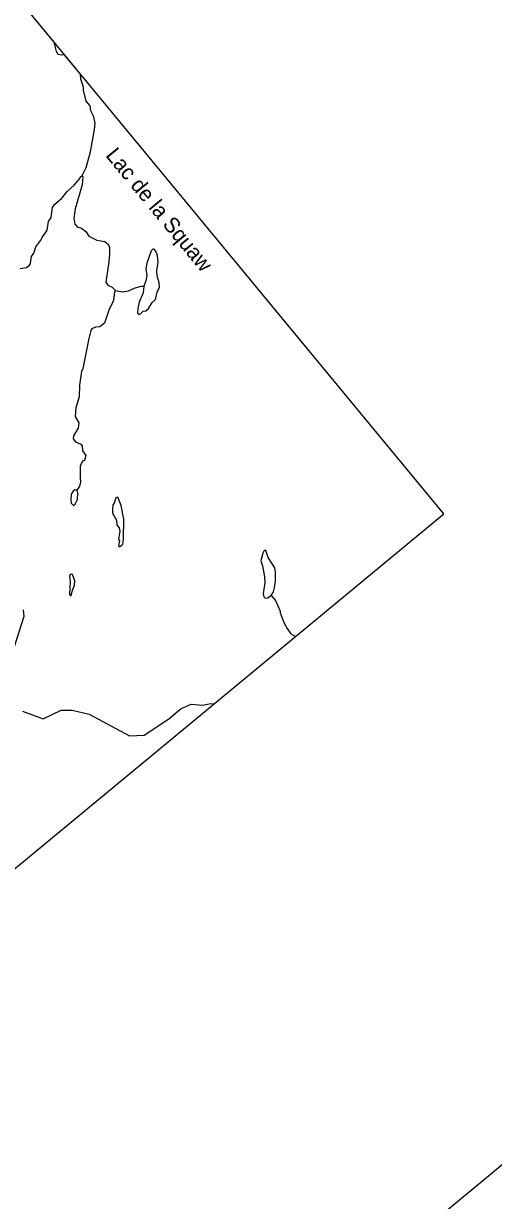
# Model space of a CAD drawing. Extents: x 347312 to 350503, y 6073086 to 6076432.
# Drawn here: x 349803.4 to 349915.2, y 6073732 to 6074011.8 of the extents above; entities that cross this region are included whole.
import ezdxf

# ---------------------------------------------------------------- set-up
doc = ezdxf.new("R2010")
doc.units = 0
doc.layers.add('Level 60', color=7, linetype='Continuous')
doc.layers.add('Level 63', color=7, linetype='Continuous')

msp = doc.modelspace()

# ---------------------------------------------------------------- linework, layer by layer
at = {"layer": 'Level 60'}
msp.add_lwpolyline([(350097.64, 6074648.45), (350470.23, 6074198.33), (349166.42, 6073119.09), (348793.83, 6073569.21)], close=True, dxfattribs=at)
at = {"layer": 'Level 63'}
msp.add_lwpolyline([(349489.82, 6073994.99), (349706.59, 6073732.65), (349903.35, 6073895.24), (349686.57, 6074157.57)], close=True, dxfattribs=at)
for points in [[(349809.31, 6073964.78), (349809.96, 6073965.68), (349810.27, 6073968.09), (349810.82, 6073968.91), (349811.91, 6073969.72), (349812, 6073969.95), (349812.28, 6073970.01), (349813.74, 6073971.93), (349815.43, 6073973.43), (349816.82, 6073974.96), (349816.87, 6073975.32), (349817.37, 6073975.72), (349818.28, 6073977.58), (349819.36, 6073981.36), (349820.31, 6073986.67), (349820.43, 6073988.17), (349820.12, 6073989.66), (349819.4, 6073991.04), (349819.27, 6073992.3), (349818.33, 6073993.35), (349817.67, 6073995.97), (349817.66, 6073996.67), (349817.01, 6073998.59), (349816.96, 6073999.78), (349813.06, 6074004.5), (349813.03, 6074004.45), (349812.53, 6074004.32), (349811.64, 6074004.49), (349811.21, 6074005.18), (349810.68, 6074007.37), (349766.44, 6074060.92)], [(349817.37, 6073975.72), (349817.54, 6073975.36), (349817.37, 6073973.44), (349815.65, 6073967.74), (349815.4, 6073965.59), (349815.62, 6073964.14), (349816.16, 6073963.53), (349817.17, 6073963.14), (349818.18, 6073962.42), (349818.92, 6073961.27), (349820.84, 6073960.29), (349822.77, 6073959.97), (349823.54, 6073959.34), (349823.85, 6073958.6), (349823.83, 6073957.18), (349823.66, 6073955.14), (349822.95, 6073950.35), (349823.41, 6073949.63), (349824.44, 6073949.15), (349825.25, 6073948.32)], [(349802.61, 6073953.57), (349804.12, 6073953.79), (349804.79, 6073954.38), (349805.08, 6073954.77), (349805.3, 6073956.41), (349805.88, 6073957.25), (349806.36, 6073958.71), (349807.54, 6073960.3), (349807.8, 6073960.99), (349808.98, 6073962.73), (349809.31, 6073964.78)], [(349831.98, 6073949.36), (349831.86, 6073947.8), (349830.93, 6073945.6), (349830.57, 6073944.07), (349830.51, 6073942.99), (349830.83, 6073942.65), (349831.31, 6073942.86), (349831.89, 6073943.43), (349832.51, 6073943.54), (349833.12, 6073944.07), (349833.98, 6073945.52), (349834.82, 6073946.24), (349835.17, 6073947.92), (349835.74, 6073949.13), (349835.68, 6073950.17), (349835.17, 6073951.83), (349835.14, 6073953.11), (349835.44, 6073955.13), (349835.27, 6073956.57), (349834.93, 6073957.55), (349834.46, 6073958.21), (349834.16, 6073958.19), (349833.75, 6073957.81), (349832.74, 6073954.84), (349832.52, 6073953.47), (349832.74, 6073951.96), (349832.49, 6073950.63), (349831.98, 6073949.36)], [(349825.25, 6073948.32), (349825.07, 6073948.07), (349824.81, 6073946.07), (349824.5, 6073945.23), (349823.77, 6073943.95), (349822.63, 6073940.6), (349821.55, 6073939.7), (349820.49, 6073939.67), (349819.62, 6073939.26), (349819.42, 6073938.83), (349818.93, 6073936.98), (349817.52, 6073929.84), (349817.22, 6073929.06), (349816.69, 6073925.82), (349816.61, 6073923.04), (349815.82, 6073920.47), (349815.65, 6073918.43), (349816.53, 6073916.91), (349816.41, 6073915.62), (349815.26, 6073913.84), (349815.2, 6073913.09), (349815.79, 6073912.36), (349817.02, 6073911.82), (349817.34, 6073911.42), (349817.45, 6073910.26), (349818.19, 6073909.11), (349817.87, 6073907.94), (349817.43, 6073907.75), (349816.9, 6073906.57), (349816.83, 6073903.91), (349816.93, 6073902.69), (349816.7, 6073901.8), (349816.08, 6073900.88)], [(349825.25, 6073948.32), (349826.91, 6073948.01), (349828.4, 6073948.26), (349829.93, 6073948.99), (349831.47, 6073949.39), (349831.98, 6073949.36)], [(349816.28, 6073900.22), (349816.08, 6073900.88), (349815.61, 6073900.99), (349815.18, 6073900.65), (349814.76, 6073899.94), (349814.63, 6073898.59), (349814.75, 6073897.76), (349815.26, 6073897.25), (349815.69, 6073897.53), (349816.21, 6073898.65), (349816.28, 6073900.22)], [(349824.67, 6073897.42), (349824.52, 6073896.38), (349824.59, 6073895.4), (349825.49, 6073893.78), (349825.59, 6073892.56), (349826.12, 6073891.95), (349826.3, 6073891.17), (349826.02, 6073889.27), (349826.23, 6073888.94), (349825.95, 6073887.64), (349826.26, 6073887.45), (349827, 6073888.03), (349827.2, 6073889.28), (349827.24, 6073893.97), (349826.59, 6073897.26), (349825.79, 6073899.23), (349825.38, 6073899.06), (349824.93, 6073897.78), (349824.67, 6073897.42)], [(349861.4, 6073875.32), (349862.28, 6073875.86), (349862.87, 6073876.7), (349863.1, 6073877.64), (349863.32, 6073879.28), (349863.35, 6073881.37), (349863.2, 6073882.38), (349861.55, 6073884.88), (349860.99, 6073886.55), (349860.66, 6073886.56), (349860.28, 6073885.93), (349859.85, 6073884.08), (349860.26, 6073882.88), (349860.71, 6073880.25), (349860.79, 6073878.91), (349860.42, 6073876.23), (349860.55, 6073875.51), (349860.88, 6073875.23), (349861.4, 6073875.32)], [(349815.62, 6073879.31), (349815.07, 6073880.82), (349814.75, 6073880.95), (349814.5, 6073880.86), (349814.33, 6073880.4), (349814.47, 6073879.05), (349814.3, 6073876.25), (349814.49, 6073875.86), (349814.76, 6073875.8), (349815.06, 6073877.07), (349815.53, 6073878.26), (349815.62, 6073879.31)], [(349862.28, 6073875.86), (349863.33, 6073874.68), (349864.45, 6073872.09), (349864.47, 6073871.73), (349865.36, 6073869.23), (349866.09, 6073867.96), (349866.97, 6073866.71), (349868.04, 6073866.06)], [(349803.28, 6073872.42), (349803.46, 6073870.82), (349800.09, 6073860.13)], [(349803.19, 6073848.32), (349808.07, 6073846.54), (349812.33, 6073848.56), (349814.95, 6073848.61), (349818.98, 6073847.63), (349828.62, 6073842.51), (349832.05, 6073842.62), (349837.99, 6073846.5), (349840.88, 6073848.95), (349843.3, 6073850), (349845.97, 6073849.78), (349847.93, 6073850.18), (349848.67, 6073850.05)]]:
    msp.add_lwpolyline(points, dxfattribs=at)

# ---------------------------------------------------------------- texts
msp.add_text('Lac de la Squaw', height=3.6667, rotation=309.568, dxfattribs=at).set_placement((349822.75, 6073980.42))

doc.saveas('drawing.dxf')
